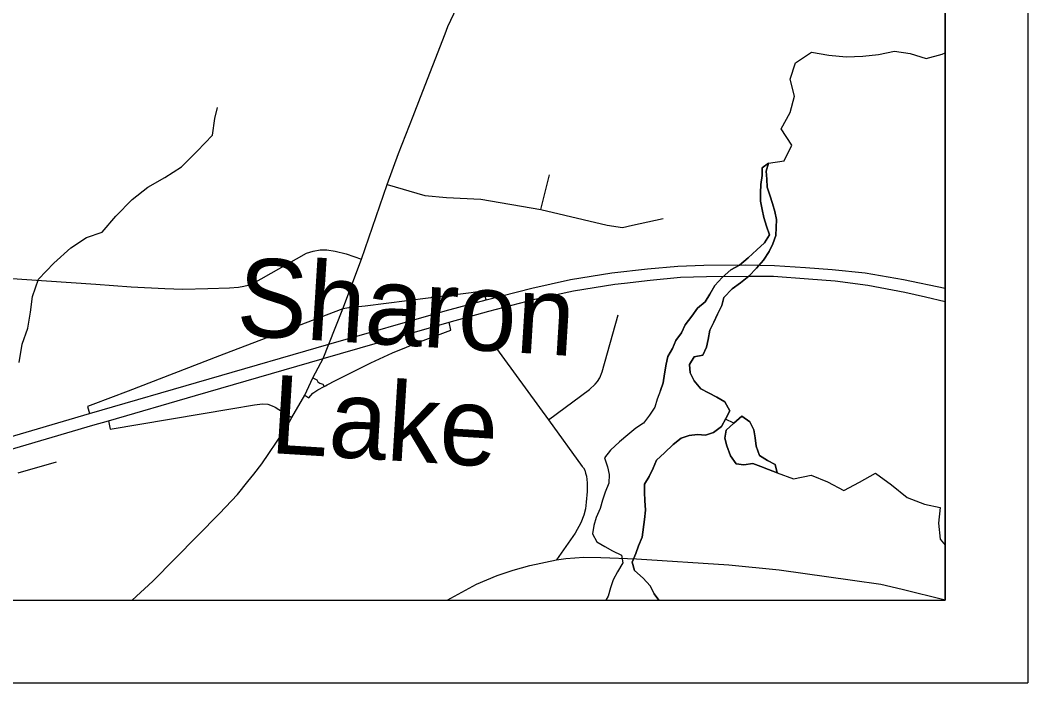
# Model space of a CAD drawing. Extents: x 0 to 34, y 0 to 22.
# Drawn here: x 7.782 to 9, y 14 to 14.8 of the extents above; entities that cross this region are included whole.
import ezdxf

# ---------------------------------------------------------------- set-up
doc = ezdxf.new("R2010")
doc.units = 0
for name, color, linetype in [('GM_X_City_Street', 7, 'Continuous'), ('GM_X_County_Road', 7, 'Continuous'), ('GM_X_Interchange_Ramps', 7, 'Continuous'), ('GM_X_Interstate_Route', 7, 'Continuous'), ('GM_X_Minor_Lake', 7, 'Continuous'), ('GM_X_Minor_Lake_Text', 7, 'Continuous'), ('GM_X_Minor_River', 7, 'Continuous'), ('GM_X_Rail_Line', 7, 'Continuous'), ('GM_X_Township_Road', 7, 'Continuous'), ('GM_X_US_Route', 7, 'Continuous'), ('SH_Cut_Line', 7, 'Continuous'), ('SH_Data', 7, 'Continuous')]:
    doc.layers.add(name, color=color, linetype=linetype)

msp = doc.modelspace()

# ---------------------------------------------------------------- linework, layer by layer
at = {"layer": 'GM_X_City_Street'}
msp.add_line((8.4115, 14.5715), (8.4218, 14.6132), dxfattribs=at)
for points in [[(8.2259, 14.6015), (8.2714, 14.5886), (8.2974, 14.5859), (8.3391, 14.5838), (8.4115, 14.5715), (8.4915, 14.5524), (8.51, 14.5496), (8.5223, 14.5524), (8.5592, 14.5606)], [(7.7323, 14.4909), (7.7845, 14.4874), (7.8738, 14.4812), (7.9165, 14.4781), (7.957, 14.476), (7.9788, 14.4754), (8.009, 14.4762), (8.0355, 14.4768), (8.0462, 14.4779), (8.0527, 14.4789), (8.0578, 14.48), (8.0663, 14.4838), (8.0734, 14.4876), (8.1284, 14.5188), (8.1363, 14.5211), (8.145, 14.5226), (8.153, 14.5227), (8.163, 14.521), (8.1761, 14.5178), (8.1948, 14.5115)], [(8.4206, 14.3174), (8.4703, 14.354), (8.4772, 14.3607), (8.4799, 14.3638), (8.4827, 14.3683), (8.4857, 14.3754), (8.5049, 14.4445)], [(8.3534, 14.4096), (8.4206, 14.3174), (8.4616, 14.2612), (8.4629, 14.2594), (8.4645, 14.2566), (8.4656, 14.2533), (8.4666, 14.2494), (8.4672, 14.2455), (8.4676, 14.2413), (8.4676, 14.2311), (8.4664, 14.2181), (8.4654, 14.2102), (8.4636, 14.2026), (8.46, 14.1932), (8.453, 14.1806), (8.4304, 14.1487)]]:
    msp.add_lwpolyline(points, dxfattribs=at)
at = {"layer": 'GM_X_County_Road'}
msp.add_lwpolyline([(8.2983, 14.1), (8.3338, 14.1191), (8.3589, 14.1297), (8.3781, 14.1362), (8.3982, 14.1418), (8.4304, 14.1487), (8.4419, 14.1502), (8.4635, 14.1517), (8.4842, 14.1515), (8.5271, 14.1499), (8.6386, 14.1423), (8.6997, 14.1364), (8.7882, 14.1239), (8.8225, 14.1193), (8.8483, 14.1131), (8.9, 14.1001)], dxfattribs=at)
at = {"layer": 'GM_X_Interchange_Ramps'}
for points in [[(8.3453, 14.4625), (8.3426, 14.4731), (8.3275, 14.4709), (8.2755, 14.4643)], [(8.2755, 14.4643), (8.1991, 14.4546), (8.1794, 14.4527), (8.1724, 14.4514)], [(8.1724, 14.4514), (8.1607, 14.447), (8.0234, 14.3949), (7.9128, 14.3522), (7.87, 14.3359), (7.8638, 14.3338), (7.8662, 14.3251)], [(8.1262, 14.3472), (8.131, 14.3443), (8.1359, 14.3496), (8.142, 14.3537), (8.1498, 14.3578), (8.1514, 14.3586), (8.1534, 14.3598), (8.1567, 14.3614), (8.1602, 14.3634), (8.206, 14.3864), (8.2323, 14.3983), (8.266, 14.4121), (8.3029, 14.4257), (8.3007, 14.4353)], [(8.1358, 14.3681), (8.1407, 14.3659), (8.1422, 14.3636), (8.1443, 14.362), (8.1479, 14.3606), (8.1498, 14.3578)], [(8.0369, 14.3309), (8.0656, 14.3358), (8.0752, 14.3368), (8.0817, 14.3363), (8.0869, 14.3346), (8.0906, 14.333), (8.1026, 14.3253), (8.1108, 14.3205)], [(7.8889, 14.3164), (7.8913, 14.3061), (8.0369, 14.3309)]]:
    msp.add_lwpolyline(points, dxfattribs=at)
at = {"layer": 'GM_X_Interstate_Route'}
for p, q in [((8.8762, 14.4659), (8.9, 14.4603)), ((7.9942, 14.3468), (8.1474, 14.3911))]:
    msp.add_line(p, q, dxfattribs=at)
for points in [[(7.758, 14.2935), (7.8662, 14.3251), (8.1553, 14.4088), (8.296, 14.4492), (8.3453, 14.4625), (8.4006, 14.4767), (8.4475, 14.4868), (8.4973, 14.4949), (8.5403, 14.4997), (8.5769, 14.5032), (8.6083, 14.5043), (8.659, 14.5048), (8.6938, 14.504), (8.7313, 14.5014), (8.7637, 14.4989), (8.8033, 14.495), (8.8498, 14.4871), (8.9, 14.4765)], [(8.5126, 14.4826), (8.5438, 14.4861), (8.5804, 14.4897), (8.6118, 14.4908), (8.6625, 14.4912), (8.6928, 14.4912), (8.7348, 14.4879), (8.7672, 14.4853), (8.8068, 14.48), (8.8513, 14.4717), (8.8762, 14.4659)], [(8.3673, 14.4536), (8.4041, 14.4631), (8.451, 14.4732), (8.5008, 14.4813), (8.5126, 14.4826)], [(8.3196, 14.4406), (8.3488, 14.4489), (8.3673, 14.4536)], [(8.1474, 14.3911), (8.1484, 14.3914), (8.3007, 14.4353), (8.3196, 14.4406)], [(7.7577, 14.278), (7.8703, 14.3109), (7.8889, 14.3164), (7.9942, 14.3468)]]:
    msp.add_lwpolyline(points, dxfattribs=at)
at = {"layer": 'GM_X_Minor_Lake'}
for points in [[(8.5541, 14.1), (8.5486, 14.1075), (8.5437, 14.117), (8.535, 14.1265), (8.5247, 14.1356), (8.5217, 14.1455), (8.5262, 14.1561), (8.5297, 14.1656), (8.5338, 14.1759), (8.5369, 14.1971), (8.538, 14.2085), (8.5373, 14.2203), (8.5369, 14.2298), (8.5369, 14.2397), (8.5426, 14.2491), (8.5471, 14.259), (8.5513, 14.2689), (8.5608, 14.2776), (8.5714, 14.2879), (8.5809, 14.2955), (8.5908, 14.2985), (8.6007, 14.3), (8.6105, 14.2989), (8.62, 14.3023), (8.6299, 14.3095), (8.6352, 14.319), (8.6398, 14.3285), (8.6337, 14.3391), (8.6242, 14.3448), (8.6143, 14.3501), (8.6048, 14.3551), (8.5969, 14.3646), (8.5919, 14.3744), (8.5912, 14.3843), (8.5969, 14.3938), (8.6071, 14.3957), (8.6117, 14.4052), (8.6136, 14.4147), (8.6159, 14.4257), (8.6204, 14.4356), (8.625, 14.445), (8.6303, 14.4557), (8.6326, 14.4652), (8.6428, 14.4758), (8.6527, 14.483), (8.6629, 14.491), (8.6721, 14.5005), (8.6804, 14.5104), (8.6876, 14.5206), (8.6918, 14.5301), (8.6956, 14.5403), (8.6964, 14.5593), (8.6941, 14.5692), (8.6914, 14.5787), (8.6884, 14.5889), (8.685, 14.5984), (8.6846, 14.6083), (8.6838, 14.6178), (8.6865, 14.6273)], [(8.6865, 14.6273), (8.6838, 14.6178), (8.6846, 14.6083), (8.685, 14.5984), (8.6884, 14.5889), (8.6914, 14.5787), (8.6941, 14.5692), (8.6964, 14.5593), (8.6956, 14.5403), (8.6918, 14.5301), (8.6876, 14.5206), (8.6804, 14.5104), (8.6721, 14.5005), (8.6629, 14.491), (8.6527, 14.483), (8.6428, 14.4758), (8.6326, 14.4652), (8.6303, 14.4557), (8.625, 14.445), (8.6204, 14.4356), (8.6159, 14.4257), (8.6136, 14.4147), (8.6117, 14.4052), (8.6071, 14.3957), (8.5969, 14.3938), (8.5912, 14.3843), (8.5919, 14.3744), (8.5969, 14.3646), (8.6048, 14.3551), (8.6143, 14.3501), (8.6242, 14.3448), (8.6337, 14.3391), (8.6398, 14.3285), (8.6352, 14.319), (8.6299, 14.3095), (8.62, 14.3023), (8.6105, 14.2989), (8.6007, 14.3), (8.5908, 14.2985), (8.5809, 14.2955), (8.5714, 14.2879), (8.5608, 14.2776), (8.5513, 14.2689), (8.5471, 14.259), (8.5426, 14.2491), (8.5369, 14.2397), (8.5369, 14.2298), (8.5373, 14.2203), (8.538, 14.2085), (8.5369, 14.1971), (8.5338, 14.1759), (8.5297, 14.1656), (8.5262, 14.1561), (8.5217, 14.1455), (8.5247, 14.1356), (8.535, 14.1265), (8.5437, 14.117), (8.5486, 14.1075), (8.5541, 14.1)], [(8.6865, 14.6273), (8.6789, 14.622), (8.6789, 14.6125), (8.6774, 14.6015), (8.677, 14.5916), (8.677, 14.5817), (8.6789, 14.5715), (8.6808, 14.562), (8.6842, 14.5514), (8.688, 14.5411), (8.6819, 14.5312), (8.6724, 14.5229), (8.6622, 14.513), (8.6515, 14.5043), (8.6409, 14.4986), (8.6307, 14.4895), (8.6219, 14.4796), (8.6159, 14.4693), (8.6102, 14.4599), (8.6007, 14.4523), (8.5938, 14.4428), (8.5859, 14.4321), (8.5813, 14.4227), (8.5745, 14.4132), (8.5707, 14.4037), (8.565, 14.3942), (8.5631, 14.3847), (8.5608, 14.3729), (8.5593, 14.3623), (8.5562, 14.3528)], [(8.5562, 14.3528), (8.5593, 14.3623), (8.5608, 14.3729), (8.5631, 14.3847), (8.565, 14.3942), (8.5707, 14.4037), (8.5745, 14.4132), (8.5813, 14.4227), (8.5859, 14.4321), (8.5938, 14.4428), (8.6007, 14.4523), (8.6102, 14.4599), (8.6159, 14.4693), (8.6219, 14.4796), (8.6307, 14.4895), (8.6409, 14.4986), (8.6515, 14.5043), (8.6622, 14.513), (8.6724, 14.5229), (8.6819, 14.5312), (8.688, 14.5411), (8.6842, 14.5514), (8.6808, 14.562), (8.6789, 14.5715), (8.677, 14.5817), (8.677, 14.5916), (8.6774, 14.6015), (8.6789, 14.6125), (8.6789, 14.622), (8.6865, 14.6273)], [(8.5562, 14.3528), (8.5521, 14.3425), (8.5494, 14.3327), (8.543, 14.3232), (8.5357, 14.3137), (8.5262, 14.3076), (8.5168, 14.2996), (8.5065, 14.2909), (8.4955, 14.281), (8.4883, 14.2715), (8.4921, 14.2609), (8.494, 14.2514), (8.4936, 14.2412), (8.4894, 14.2302), (8.486, 14.2207), (8.4833, 14.2104), (8.4784, 14.1998), (8.4757, 14.1899), (8.4738, 14.18), (8.4792, 14.1702), (8.4887, 14.1645), (8.4981, 14.1592), (8.5088, 14.1542), (8.5107, 14.1447), (8.5042, 14.1341), (8.4989, 14.1242), (8.4955, 14.1147), (8.4928, 14.1045), (8.4899, 14.1)], [(8.6447, 14.3137), (8.6542, 14.322), (8.6641, 14.3152), (8.669, 14.3053), (8.6705, 14.2958), (8.6717, 14.2856), (8.6758, 14.2746), (8.6853, 14.2685), (8.6948, 14.2636), (8.6971, 14.2537), (8.6868, 14.2575), (8.6774, 14.2613), (8.6675, 14.2647), (8.6569, 14.2632), (8.6474, 14.2643), (8.6405, 14.2742), (8.6364, 14.286), (8.6337, 14.2955), (8.6356, 14.305), (8.6447, 14.3137)], [(8.6971, 14.2537), (8.6948, 14.2636), (8.6853, 14.2685), (8.6758, 14.2746), (8.6717, 14.2856), (8.6705, 14.2958), (8.669, 14.3053), (8.6641, 14.3152), (8.6542, 14.322), (8.6447, 14.3137)], [(8.6447, 14.3137), (8.6356, 14.305), (8.6337, 14.2955), (8.6364, 14.286), (8.6405, 14.2742), (8.6474, 14.2643), (8.6569, 14.2632), (8.6675, 14.2647), (8.6774, 14.2613), (8.6868, 14.2575), (8.6971, 14.2537)]]:
    msp.add_lwpolyline(points, dxfattribs=at)
at = {"layer": 'GM_X_Minor_River'}
msp.add_line((8.6447, 14.3137), (8.6347, 14.3182), dxfattribs=at)
for points in [[(8.6865, 14.6273), (8.7055, 14.6303), (8.715, 14.6493), (8.702, 14.6687), (8.7127, 14.6888), (8.718, 14.7085), (8.7127, 14.7287), (8.7191, 14.7484), (8.7385, 14.7613), (8.7594, 14.7579), (8.7803, 14.756), (8.8008, 14.7568), (8.8197, 14.7586), (8.8387, 14.7628), (8.8577, 14.7598), (8.8771, 14.7537), (8.8964, 14.759), (8.9, 14.7608)], [(7.7813, 14.3866), (7.7847, 14.409), (7.7916, 14.4284), (7.795, 14.4474), (7.7973, 14.4663), (7.8045, 14.4872), (7.8231, 14.5066), (7.8436, 14.5252), (7.8626, 14.5377), (7.8816, 14.5442), (7.8979, 14.5635), (7.9176, 14.5836), (7.9366, 14.5985), (7.9571, 14.6102), (7.9772, 14.6231), (7.9962, 14.6421), (8.0148, 14.6611), (8.0175, 14.6812), (8.0209, 14.6945)], [(8.6971, 14.2537), (8.7168, 14.2465), (8.7381, 14.2507), (8.7578, 14.2427), (8.7776, 14.2321), (8.7966, 14.2423), (8.8159, 14.2533), (8.8353, 14.2389), (8.8543, 14.2237), (8.8752, 14.2157), (8.8941, 14.2115), (8.8922, 14.1926), (8.8941, 14.1736), (8.9, 14.1661)]]:
    msp.add_lwpolyline(points, dxfattribs=at)
at = {"layer": 'GM_X_Rail_Line'}
msp.add_line((7.7798, 14.2537), (7.8264, 14.2669), dxfattribs=at)
at = {"layer": 'GM_X_Township_Road'}
msp.add_lwpolyline([(5.2869, 14.1), (8.9, 14.1), (8.9, 14.8595), (8.5293, 14.9371), (8.525, 14.938), (8.3833, 14.9688), (8.168, 14.9819), (7.6752, 15.0122), (7.6301, 15.0148), (7.437, 15.0262), (7.3636, 15.0306), (6.9119, 15.0636), (6.488, 15.0839), (6.401, 15.0917), (6.3032, 15.1064), (5.9659, 15.1626)], dxfattribs=at)
at = {"layer": 'GM_X_US_Route'}
for p, q in [((8.266, 14.7071), (8.2958, 14.7837)), ((8.1948, 14.5115), (8.2259, 14.6015)), ((8.1724, 14.4514), (8.1948, 14.5115))]:
    msp.add_line(p, q, dxfattribs=at)
for points in [[(8.2958, 14.7837), (8.2992, 14.7923), (8.3384, 14.8761)], [(8.2259, 14.6015), (8.2397, 14.6393), (8.2571, 14.6841), (8.266, 14.7071)], [(8.1457, 14.3865), (8.1484, 14.3914), (8.1553, 14.4088), (8.1724, 14.4514)], [(8.1056, 14.3117), (8.1108, 14.3205), (8.1262, 14.3472), (8.1358, 14.3681), (8.1457, 14.3865)], [(8.0646, 14.252), (8.0743, 14.2643), (8.1004, 14.303), (8.1056, 14.3117)], [(7.9177, 14.1), (7.9425, 14.1229), (8.0233, 14.2045), (8.0451, 14.2274), (8.0574, 14.243), (8.0646, 14.252)]]:
    msp.add_lwpolyline(points, dxfattribs=at)
at = {"layer": 'SH_Cut_Line'}
msp.add_lwpolyline([(2.1, 14.1), (8.9, 14.1), (8.9, 14.8595), (8.5293, 14.9371), (8.525, 14.938), (8.3833, 14.9688), (8.168, 14.9819), (7.6752, 15.0122), (7.6301, 15.0148), (7.437, 15.0262), (7.3636, 15.0306), (6.9119, 15.0636), (6.488, 15.0839), (6.401, 15.0917), (6.3032, 15.1064), (5.9659, 15.1626)], dxfattribs=at)
at = {"layer": 'SH_Data'}
for p, q in [((9, 21), (9, 14)), ((8.9, 20.9), (8.9, 14.1)), ((2.1, 14.1), (8.9, 14.1)), ((2, 14), (9, 14))]:
    msp.add_line(p, q, dxfattribs=at)

# ---------------------------------------------------------------- texts
at = {"layer": 'GM_X_Minor_Lake_Text'}
for s, rotation, p in [('Sharon', 356.4652, (8.0424, 14.4197)), ('Lake', 356.4651, (8.0831, 14.2776))]:
    msp.add_text(s, height=0.09469, rotation=rotation, dxfattribs=at).set_placement(p)

doc.saveas('drawing.dxf')
